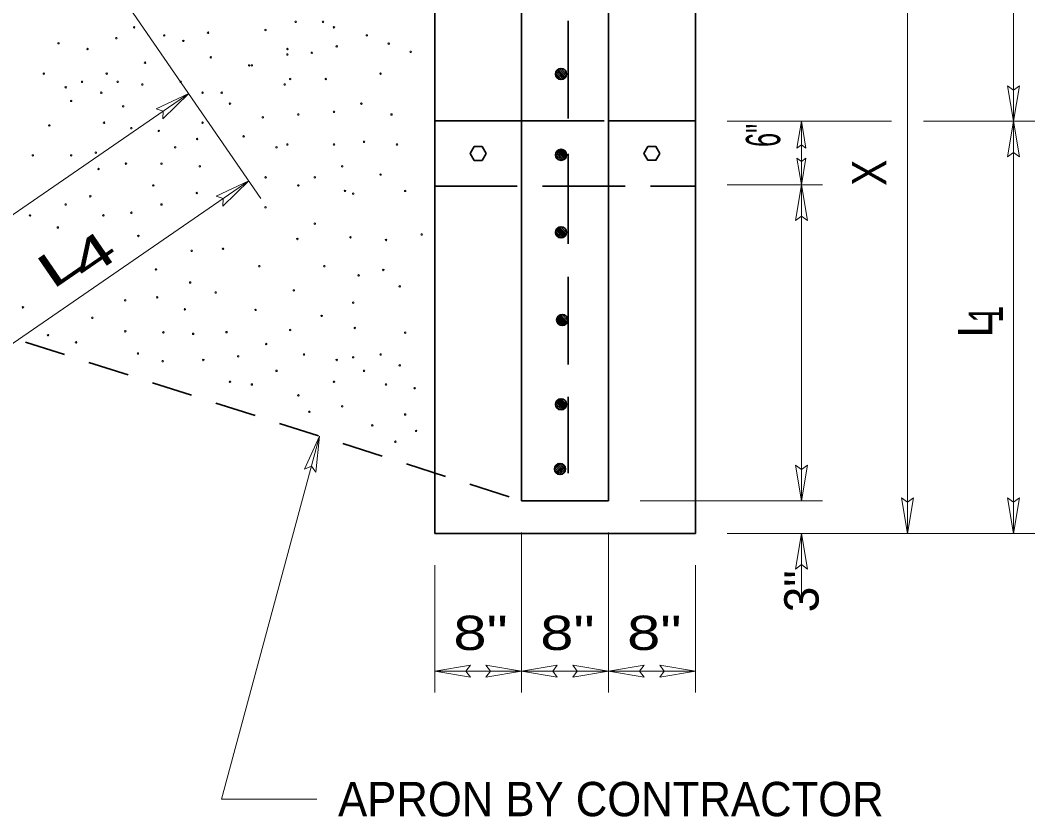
# Model space of a CAD drawing. Extents: x 178962.5 to 178977.5, y 178951.2 to 178972.9.
# Drawn here: x 178973.406 to 178977.392, y 178966.66 to 178969.79 of the extents above; entities that cross this region are included whole.
import ezdxf
from ezdxf.enums import TextEntityAlignment as Align

# ---------------------------------------------------------------- set-up
doc = ezdxf.new("R2010")
doc.units = 0
doc.header["$LTSCALE"] = 0.054
doc.linetypes.add('LONG_DASHED', pattern=[7.5, 6, -1.5])
doc.linetypes.add('MEDIUM_DASHED', pattern=[4.5, 3, -1.5])
for name, color, linetype, lineweight in [('1', 7, 'Continuous', 35), ('10', 7, 'Continuous', 13), ('12', 7, 'Continuous', 53), ('6', 7, 'Continuous', 13)]:
    doc.layers.add(name, color=color, linetype=linetype, lineweight=lineweight)

msp = doc.modelspace()

# ---------------------------------------------------------------- linework, layer by layer
at = {"layer": '1'}
for p, q in [((178976.05883, 178971.18683), (178976.05883, 178967.7735)), ((178975.7175, 178970.8455), (178975.7175, 178967.9015)), ((178975.37617, 178970.50417), (178975.37617, 178967.9015)), ((178975.03483, 178970.16283), (178975.03483, 178967.7735)), ((178975.55917, 178969.40367), (178975.55917, 178969.7885)), ((178975.50983, 178969.58375), (178975.5335, 178969.55725)), ((178975.51217, 178969.58942), (178975.5395, 178969.55875)), ((178975.51542, 178969.59392), (178975.54442, 178969.5615)), ((178975.51967, 178969.59742), (178975.54825, 178969.56533)), ((178975.52475, 178969.59975), (178975.55125, 178969.57017)), ((178975.53117, 178969.60075), (178975.55292, 178969.5765)), ((178975.54025, 178969.59892), (178975.55208, 178969.58575)), ((178975.50967, 178969.57575), (178975.52567, 178969.55783)), ((178975.03483, 178969.39483), (178975.37617, 178969.39483)), ((178976.05883, 178969.39483), (178975.7175, 178969.39483)), ((178975.50983, 178969.26592), (178975.5335, 178969.23942)), ((178975.51217, 178969.27175), (178975.5395, 178969.241)), ((178975.51542, 178969.27617), (178975.54442, 178969.24375)), ((178975.51967, 178969.27975), (178975.54825, 178969.24758)), ((178975.52475, 178969.28208), (178975.55125, 178969.2525)), ((178975.53117, 178969.28308), (178975.55292, 178969.25875)), ((178975.54025, 178969.28108), (178975.55208, 178969.268)), ((178975.55917, 178968.91133), (178975.55917, 178969.26483)), ((178975.50967, 178969.25808), (178975.52567, 178969.24008)), ((178975.50967, 178968.95367), (178975.52567, 178968.93575)), ((178975.50983, 178968.96158), (178975.5335, 178968.93508)), ((178975.51217, 178968.96733), (178975.5395, 178968.93658)), ((178975.51542, 178968.97175), (178975.54442, 178968.93942)), ((178975.51967, 178968.97533), (178975.54825, 178968.94317)), ((178975.52475, 178968.97775), (178975.55125, 178968.94808)), ((178975.53117, 178968.97867), (178975.55292, 178968.95442)), ((178975.54025, 178968.97675), (178975.55208, 178968.96367)), ((178975.55917, 178968.43683), (178975.55917, 178968.78142)), ((178975.5165, 178968.62275), (178975.54392, 178968.592)), ((178975.51983, 178968.62717), (178975.54883, 178968.59475)), ((178975.52408, 178968.63067), (178975.55275, 178968.59858)), ((178975.52917, 178968.63308), (178975.55567, 178968.60342)), ((178975.53567, 178968.63408), (178975.55742, 178968.60975)), ((178975.54475, 178968.63208), (178975.5565, 178968.619)), ((178975.51408, 178968.60908), (178975.53008, 178968.59108)), ((178975.51433, 178968.617), (178975.538, 178968.5905)), ((178975.52475, 178968.30183), (178975.55125, 178968.27225)), ((178975.53117, 178968.30283), (178975.55292, 178968.2785)), ((178975.55917, 178968.00983), (178975.55917, 178968.31083)), ((178975.50967, 178968.27783), (178975.52567, 178968.25983)), ((178975.50983, 178968.28575), (178975.5335, 178968.25925)), ((178975.51217, 178968.29142), (178975.5395, 178968.26075)), ((178975.51542, 178968.296), (178975.54442, 178968.2635)), ((178975.51967, 178968.29942), (178975.54825, 178968.26733)), ((178975.54025, 178968.30092), (178975.55208, 178968.28775)), ((178975.53167, 178968.048), (178975.50525, 178968.02425)), ((178975.52383, 178968.04817), (178975.50583, 178968.03217)), ((178975.5375, 178968.04575), (178975.50675, 178968.01842)), ((178975.54192, 178968.04242), (178975.5095, 178968.01342)), ((178975.5455, 178968.03817), (178975.51325, 178968.00958)), ((178975.54783, 178968.03308), (178975.51817, 178968.00658)), ((178975.54883, 178968.02667), (178975.5245, 178968.00492)), ((178975.54683, 178968.01758), (178975.53375, 178968.00575)), ((178975.37617, 178967.9015), (178975.7175, 178967.9015)), ((178975.03483, 178967.7735), (178976.05883, 178967.7735))]:
    msp.add_line(p, q, dxfattribs=at)
at = {"layer": '1', "linetype": 'LONG_DASHED'}
for p, q in [((178975.37617, 178969.39483), (178975.7175, 178969.39483)), ((178975.03483, 178969.13883), (178976.05883, 178969.13883))]:
    msp.add_line(p, q, dxfattribs=at)
at = {"layer": '1', "linetype": 'MEDIUM_DASHED'}
msp.add_line((178971.42992, 178969.16417), (178975.37617, 178967.9015), dxfattribs=at)
at = {"layer": '1'}
for points in [[(178975.23675, 178969.26683), (178975.22117, 178969.23975), (178975.18992, 178969.23975), (178975.17425, 178969.26683), (178975.18992, 178969.29383), (178975.22117, 178969.29383)], [(178975.91942, 178969.26683), (178975.90383, 178969.23983), (178975.87258, 178969.23983), (178975.85692, 178969.26683), (178975.87258, 178969.29392), (178975.90383, 178969.29392)]]:
    msp.add_lwpolyline(points, close=True, dxfattribs=at)
for centre in [(178975.53125, 178969.57896), (178975.53125, 178969.26123), (178975.53125, 178968.95684), (178975.53569, 178968.61222), (178975.53125, 178968.281), (178975.52697, 178968.02658)]:
    msp.add_circle(centre, 0.02184, dxfattribs=at)
at = {"layer": '10'}
for p, q in [((178977.309, 178971.18683), (178977.309, 178969.39308)), ((178976.89233, 178967.7735), (178976.89233, 178970.5895)), ((178973.45008, 178970.40117), (178974.35142, 178969.09)), ((178972.11883, 178968.16183), (178974.06817, 178969.50183)), ((178973.93958, 178969.44175), (178974.06817, 178969.50183)), ((178973.966, 178969.40333), (178974.06817, 178969.50183)), ((178977.28567, 178969.53308), (178977.309, 178969.39308)), ((178977.28567, 178969.53308), (178977.309, 178969.51558)), ((178977.33233, 178969.53308), (178977.309, 178969.39308)), ((178977.33233, 178969.53308), (178977.309, 178969.51558)), ((178973.93958, 178969.44175), (178973.96725, 178969.43242)), ((178973.966, 178969.40333), (178973.96725, 178969.43242)), ((178976.18383, 178969.39308), (178976.82983, 178969.39308)), ((178976.45817, 178969.28808), (178976.47567, 178969.39308)), ((178976.47567, 178969.39308), (178976.47567, 178969.14342)), ((178976.49317, 178969.28808), (178976.47567, 178969.39308)), ((178977.39233, 178969.39308), (178976.95483, 178969.39308)), ((178977.28567, 178969.25308), (178977.309, 178969.39308)), ((178977.309, 178967.7735), (178977.309, 178969.39308)), ((178977.33233, 178969.25308), (178977.309, 178969.39308)), ((178976.45817, 178969.28808), (178976.47567, 178969.30117)), ((178976.49317, 178969.28808), (178976.47567, 178969.30117)), ((178977.28567, 178969.25308), (178977.309, 178969.27058)), ((178977.33233, 178969.25308), (178977.309, 178969.27058)), ((178976.45817, 178969.24842), (178976.47567, 178969.14342)), ((178976.45817, 178969.24842), (178976.47567, 178969.23533)), ((178976.49317, 178969.24842), (178976.47567, 178969.14342)), ((178976.49317, 178969.24842), (178976.47567, 178969.23533)), ((178974.30425, 178969.15858), (178973.05517, 178968.29992)), ((178974.17567, 178969.0985), (178974.30425, 178969.15858)), ((178974.20208, 178969.06008), (178974.30425, 178969.15858)), ((178976.18383, 178969.14342), (178976.559, 178969.14342)), ((178976.45233, 178969.00342), (178976.47567, 178969.14342)), ((178976.47567, 178969.14342), (178976.47567, 178967.9015)), ((178976.499, 178969.00342), (178976.47567, 178969.14342)), ((178974.17567, 178969.0985), (178974.20333, 178969.08917)), ((178974.20208, 178969.06008), (178974.20333, 178969.08917)), ((178976.45233, 178969.00342), (178976.47567, 178969.02092)), ((178976.499, 178969.00342), (178976.47567, 178969.02092)), ((178974.58225, 178968.1555), (178974.19692, 178966.72933)), ((178974.52317, 178968.02642), (178974.58225, 178968.1555)), ((178974.56825, 178968.01425), (178974.58225, 178968.1555)), ((178974.52317, 178968.02642), (178974.55033, 178968.03725)), ((178974.56825, 178968.01425), (178974.55033, 178968.03725)), ((178976.45233, 178968.0415), (178976.47567, 178967.9015)), ((178976.45233, 178968.0415), (178976.47567, 178968.024)), ((178976.499, 178968.0415), (178976.47567, 178967.9015)), ((178976.499, 178968.0415), (178976.47567, 178968.024)), ((178976.869, 178967.9135), (178976.89233, 178967.7735)), ((178976.869, 178967.9135), (178976.89233, 178967.896)), ((178976.91567, 178967.9135), (178976.89233, 178967.7735)), ((178976.91567, 178967.9135), (178976.89233, 178967.896)), ((178977.28567, 178967.9135), (178977.309, 178967.7735)), ((178977.28567, 178967.9135), (178977.309, 178967.896)), ((178977.33233, 178967.9135), (178977.309, 178967.7735)), ((178977.33233, 178967.9135), (178977.309, 178967.896)), ((178976.559, 178967.9015), (178975.8425, 178967.9015)), ((178975.37617, 178967.1485), (178975.37617, 178967.7765)), ((178975.7175, 178967.1485), (178975.7175, 178967.7765)), ((178977.39233, 178967.7735), (178976.18383, 178967.7735)), ((178976.45233, 178967.6335), (178976.47567, 178967.7735)), ((178976.47567, 178967.5235), (178976.47567, 178967.7735)), ((178976.499, 178967.6335), (178976.47567, 178967.7735)), ((178975.03483, 178967.1485), (178975.03483, 178967.6485)), ((178976.05883, 178967.1485), (178976.05883, 178967.6485)), ((178976.45233, 178967.6335), (178976.47567, 178967.651)), ((178976.499, 178967.6335), (178976.47567, 178967.651)), ((178975.17483, 178967.25517), (178975.03483, 178967.23183)), ((178975.17483, 178967.2085), (178975.03483, 178967.23183)), ((178975.17483, 178967.25517), (178975.15733, 178967.23183)), ((178975.17483, 178967.2085), (178975.15733, 178967.23183)), ((178975.23617, 178967.25517), (178975.37617, 178967.23183)), ((178975.23617, 178967.25517), (178975.25367, 178967.23183)), ((178975.23617, 178967.2085), (178975.37617, 178967.23183)), ((178975.23617, 178967.2085), (178975.25367, 178967.23183)), ((178975.51617, 178967.25517), (178975.37617, 178967.23183)), ((178975.51617, 178967.2085), (178975.37617, 178967.23183)), ((178975.51617, 178967.25517), (178975.49867, 178967.23183)), ((178975.51617, 178967.2085), (178975.49867, 178967.23183)), ((178975.5775, 178967.25517), (178975.7175, 178967.23183)), ((178975.5775, 178967.25517), (178975.595, 178967.23183)), ((178975.5775, 178967.2085), (178975.7175, 178967.23183)), ((178975.5775, 178967.2085), (178975.595, 178967.23183)), ((178975.8575, 178967.25517), (178975.7175, 178967.23183)), ((178976.05883, 178967.23183), (178975.7175, 178967.23183)), ((178975.8575, 178967.2085), (178975.7175, 178967.23183)), ((178975.8575, 178967.25517), (178975.84, 178967.23183)), ((178975.8575, 178967.2085), (178975.84, 178967.23183)), ((178975.91883, 178967.25517), (178976.05883, 178967.23183)), ((178975.91883, 178967.25517), (178975.93633, 178967.23183)), ((178975.91883, 178967.2085), (178976.05883, 178967.23183)), ((178975.91883, 178967.2085), (178975.93633, 178967.23183)), ((178974.19692, 178966.72933), (178974.57175, 178966.72933))]:
    msp.add_line(p, q, dxfattribs=at)
msp.add_lwpolyline([(178975.03483, 178967.23183), (178975.37617, 178967.23183), (178975.7175, 178967.23183)], dxfattribs=at)
at = {"layer": '6'}
for centre in [(178974.48837, 178969.78421), (178974.59587, 178969.78421), (178973.85362, 178969.76279), (178974.14412, 178969.74137), (178974.36996, 178969.75204), (178974.63896, 178969.76279), (178973.55633, 178969.70005), (178973.78353, 178969.71994), (178973.97196, 178969.73062), (178974.04729, 178969.70921), (178974.76804, 178969.73062), (178974.85412, 178969.69846), (178973.67071, 178969.67704), (178974.45604, 178969.67704), (178974.45604, 178969.65562), (178974.55161, 178969.66252), (178974.64971, 178969.68779), (178974.94021, 178969.66629), (178973.89662, 178969.62346), (178974.15488, 178969.64487), (178973.49863, 178969.58063), (178973.74604, 178969.58063), (178974.30546, 178969.61271), (178974.31621, 178969.61271), (178974.82187, 178969.58063), (178973.64921, 178969.54846), (178973.78904, 178969.54846), (178973.88588, 178969.53771), (178974.03654, 178969.54846), (178974.44529, 178969.53771), (178974.46687, 178969.55912), (178974.60671, 178969.55912), (178973.58471, 178969.52696), (178973.72454, 178969.50554), (178974.12254, 178969.50554), (178974.19787, 178969.50554), (178973.60621, 178969.47338), (178974.23013, 178969.46271), (178974.74654, 178969.46271), (178973.81062, 178969.45196), (178974.49913, 178969.41979), (178974.63896, 178969.43054), (178974.86487, 178969.41979), (178973.52012, 178969.37696), (178973.73529, 178969.38763), (178974.12254, 178969.38763), (178974.35929, 178969.40913), (178973.84288, 178969.36621), (178973.95046, 178969.35546), (178974.10104, 178969.32338), (178974.28396, 178969.33404), (178974.45604, 178969.30188), (178974.63896, 178969.30188), (178974.75729, 178969.31262), (178974.88638, 178969.30188), (178973.45554, 178969.25904), (178973.60621, 178969.25904), (178973.70304, 178969.26971), (178974.01496, 178969.29121), (178974.41304, 178969.29121), (178973.82137, 178969.22687), (178973.96121, 178969.22687), (178974.11179, 178969.21613), (178974.67121, 178969.21613), (178973.71379, 178969.20546), (178974.82187, 178969.18396), (178973.92896, 178969.14112), (178974.37015, 178969.17288), (178974.49913, 178969.14112), (178974.56362, 178969.17329), (178973.68154, 178969.09829), (178974.09977, 178969.11121), (178974.68196, 178969.11971), (178974.71429, 178969.10896), (178974.91862, 178969.11971), (178973.58462, 178969.06612), (178973.96121, 178969.06612), (178973.44479, 178969.02321), (178973.73299, 178969.02352), (178973.84288, 178969.03396), (178974.36996, 178969.05537), (178974.56362, 178968.99104), (178973.55393, 178968.97577), (178973.87028, 178968.94248), (178974.70354, 178968.93746), (178974.98321, 178968.94821), (178974.49515, 178968.9307), (178974.84337, 178968.92679), (178974.07964, 178968.88407), (178974.20293, 178968.89214), (178974.34589, 178968.82377), (178974.60117, 178968.82395), (178973.93936, 178968.81086), (178974.73579, 178968.78746), (178974.83262, 178968.80887), (178974.07386, 178968.75969), (178974.89712, 178968.74454), (178973.94443, 178968.70138), (178974.17371, 178968.72042), (178974.48125, 178968.72836), (178973.41663, 178968.66203), (178973.81828, 178968.68926), (178974.71429, 178968.68021), (178973.68953, 178968.62078), (178974.05316, 178968.65391), (178974.33078, 178968.652), (178974.59045, 178968.62835), (178974.72061, 178968.58094), (178973.51536, 178968.55244), (178973.81907, 178968.56783), (178973.96858, 178968.56343), (178974.08561, 178968.55794), (178974.21655, 178968.56442), (178974.46679, 178968.57304), (178974.91862, 178968.56237), (178973.62541, 178968.52433), (178974.37269, 178968.51777), (178973.86844, 178968.48044), (178974.26236, 178968.46952), (178974.52063, 178968.47662), (178974.71429, 178968.46587), (178974.82187, 178968.47662), (178973.96593, 178968.45055), (178974.12545, 178968.45516), (178974.64971, 178968.45513), (178974.89712, 178968.43371), (178974.41304, 178968.41229), (178974.75729, 178968.41229), (178974.23013, 178968.36937), (178974.31621, 178968.35871), (178974.63896, 178968.36937), (178974.84337, 178968.35871), (178974.95587, 178968.3441), (178974.49913, 178968.31579), (178974.67121, 178968.27296), (178974.54213, 178968.25154), (178974.91862, 178968.24079), (178974.78954, 178968.19787), (178974.96171, 178968.17646), (178974.88004, 178968.13367)]:
    msp.add_circle(centre, 0.00298, dxfattribs=at)

# ---------------------------------------------------------------- texts
at = {"layer": '12'}
for s, rotation, width, p in [('6"', 90, 0.55, (178976.39233, 178969.33767)), ('X', 90, 0.85, (178976.80892, 178969.19096)), ('4', 34.508, 1.7, (178973.72876, 178968.81346)), ('L', 34.504, 1.7, (178973.60214, 178968.77701)), ('1', 90, 0.65, (178977.26725, 178968.63446))]:
    msp.add_text(s, height=0.135, rotation=rotation, dxfattribs=dict(at, width=width)).set_placement(p, align=Align.CENTER)
msp.add_text('L', height=0.135, rotation=90, dxfattribs=at).set_placement((178977.22558, 178968.59279), align=Align.CENTER)
msp.add_text('3"', height=0.135, rotation=90, dxfattribs=at).set_placement((178976.54317, 178967.62804), align=Align.RIGHT)
at = {"layer": '12', "width": 1.3}
for p in [(178975.21496, 178967.31517), (178975.55629, 178967.31517), (178975.89762, 178967.31517)]:
    msp.add_text('8"', height=0.135, dxfattribs=at).set_placement(p, align=Align.CENTER)
at = {"layer": '12', "width": 0.95}
msp.add_text('APRON BY CONTRACTOR', height=0.135, dxfattribs=at).set_placement((178974.65508, 178966.66183))

doc.saveas('drawing.dxf')
